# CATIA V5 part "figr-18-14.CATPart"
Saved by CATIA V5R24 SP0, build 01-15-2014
Part number: Part1
Bounding box of the stored display mesh (mm): x -135 to 135, y -70 to 70, z 0 to 30
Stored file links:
  D:\KAVITA\CATIA V5-6R2014 Project_ Kavita\CATIA V5-6R2014_partfiles\Partfiles\c17_caia_v6-6r2014_prt\figr-17-14.CATPart
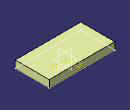
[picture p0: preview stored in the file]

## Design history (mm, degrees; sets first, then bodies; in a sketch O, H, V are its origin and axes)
Body1 (main body)
  Sketch1 on xy-plane, origin (0, 0, 0), H (1, 0, 0), V (0, 1, 0)
    line L1 (135, 70) -> (135, -70)
    line L2 (135, -70) -> (-135, -70)
    line L3 (-135, -70) -> (-135, 70)
    line L4 (-135, 70) -> (135, 70)
    length L2 = 270
    length L1 = 140
    vertical: L1 V, L3 V
    horizontal: L2 H, L4 H
    equidistance: L1 L3 O, L2 L4 O
  Extrude1: Lim1 30, Lim2 0, Element1 Sketch1
  DatumSurface1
